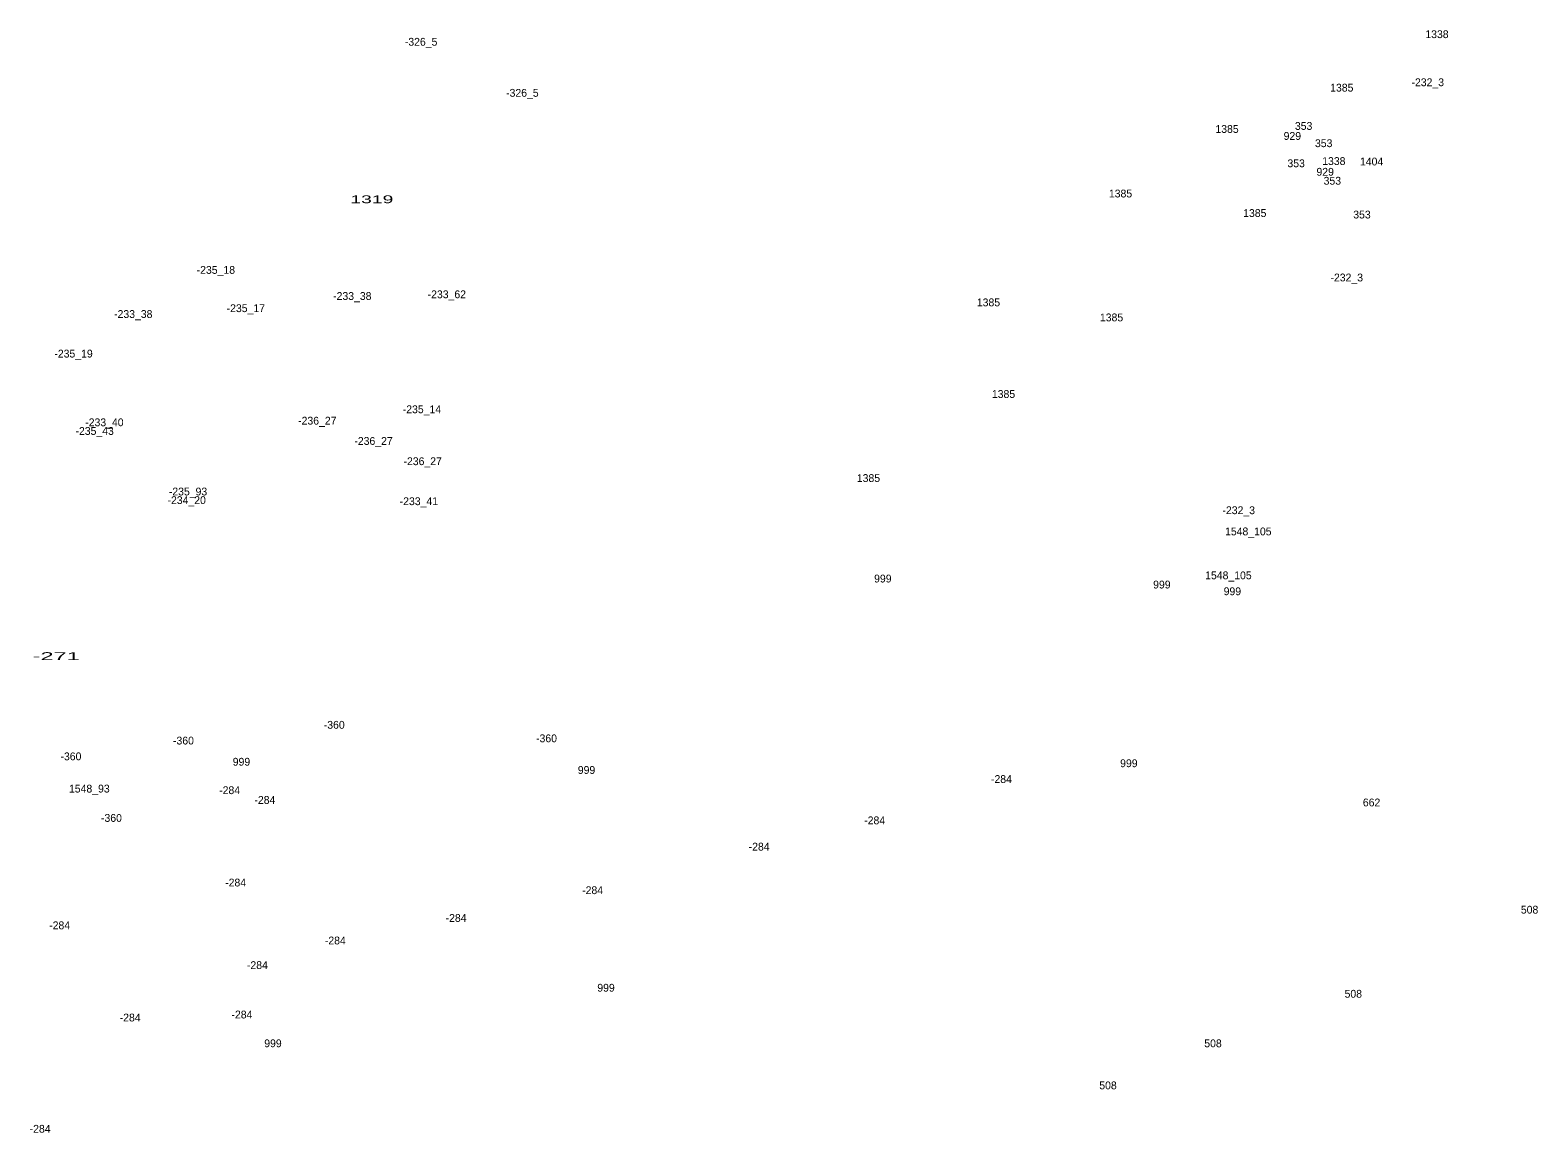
# Model space of a CAD drawing. Extents: x -660434 to -656144, y -997850 to -994016.
# Drawn here: x -656916 to -656144, y -995990 to -995426 of the extents above; entities that cross this region are included whole.
import ezdxf
from ezdxf.enums import TextEntityAlignment as Align

# ---------------------------------------------------------------- set-up
doc = ezdxf.new("R2010")
doc.units = 0
doc.header["$LTSCALE"] = 1.6
doc.layers.add('24', color=7, linetype='Continuous')

msp = doc.modelspace()

# ---------------------------------------------------------------- texts
at = {"layer": '24'}
for s, p in [('1338', (-656195.86, -995430.18)), ('-326_5', (-656715.918, -995434.07)), ('-232_3', (-656200.582, -995454.78)), ('-326_5', (-656664.078, -995460.19)), ('1385', (-656244.59, -995457.54)), ('353', (-656264.127, -995477.13)), ('1385', (-656303.34, -995478.67)), ('929', (-656269.908, -995482.25)), ('353', (-656253.857, -995485.96)), ('353', (-656267.967, -995496.24)), ('929', (-656253.108, -995500.59)), ('1338', (-656248.67, -995495.11)), ('1404', (-656229.342, -995495.33)), ('353', (-656249.437, -995505.17)), ('1385', (-656357.87, -995511.7)), ('1385', (-656289.13, -995521.69)), ('353', (-656234.267, -995522.46)), ('-235_18', (-656820.985, -995550.78)), ('-232_3', (-656242.052, -995554.66)), ('-235_17', (-656805.641, -995570.37)), ('-233_38', (-656751.141, -995564.14)), ('-233_62', (-656702.747, -995563.27)), ('1385', (-656425.46, -995567.4)), ('-233_38', (-656863.271, -995573.36)), ('1385', (-656362.47, -995575.09)), ('-235_19', (-656893.841, -995593.61)), ('1385', (-656417.77, -995614.28)), ('-235_14', (-656715.489, -995622.09)), ('-233_40', (-656878.04, -995628.77)), ('-236_27', (-656769.063, -995627.92)), ('-235_43', (-656883.026, -995633.19)), ('-236_27', (-656740.263, -995638.3)), ('-236_27', (-656715.113, -995648.67)), ('1385', (-656486.9, -995657.29)), ('-234_20', (-656835.91, -995668.58)), ('-235_93', (-656835.237, -995664.17)), ('-233_41', (-656717.059, -995669.13)), ('-232_3', (-656297.352, -995673.75)), ('1548_105', (-656292.46, -995684.58)), ('999', (-656479.553, -995708.69)), ('1548_105', (-656302.63, -995707.06)), ('999', (-656336.703, -995711.77)), ('999', (-656300.603, -995715.22)), ('-360', (-656760.384, -995783.54)), ('-360', (-656837.574, -995791.6)), ('-360', (-656651.714, -995790.45)), ('-360', (-656895.174, -995799.67)), ('999', (-656807.883, -995802.43)), ('999', (-656631.233, -995806.65)), ('999', (-656353.593, -995803.2)), ('1548_93', (-656885.757, -995816.17)), ('-284', (-656813.939, -995816.98)), ('-284', (-656418.829, -995811.29)), ('-284', (-656795.889, -995821.97)), ('662', (-656229.348, -995823.26)), ('-360', (-656874.434, -995831.17)), ('-284', (-656483.729, -995832.42)), ('-284', (-656542.869, -995845.87)), ('-284', (-656810.869, -995864.23)), ('-284', (-656628.119, -995868.15)), ('508', (-656148.461, -995878.12)), ('-284', (-656900.959, -995886.13)), ('-284', (-656698.009, -995882.36)), ('-284', (-656759.829, -995893.88)), ('-284', (-656799.729, -995906.49)), ('999', (-656621.253, -995918.06)), ('508', (-656238.711, -995921.15)), ('-284', (-656864.859, -995933.29)), ('-284', (-656807.639, -995931.75)), ('999', (-656791.753, -995946.49)), ('508', (-656310.521, -995946.5)), ('508', (-656364.281, -995968.01)), ('-284', (-656910.939, -995990.23))]:
    msp.add_text(s, height=4, dxfattribs=at).set_placement(p, align=Align.CENTER)
for s, width, p in [('1319', 1.85, (-656741.139, -995514.65)), ('-271', 2.25, (-656902.725, -995748.4))]:
    msp.add_text(s, height=4, dxfattribs=dict(at, width=width)).set_placement(p, align=Align.CENTER)

doc.saveas('drawing.dxf')
